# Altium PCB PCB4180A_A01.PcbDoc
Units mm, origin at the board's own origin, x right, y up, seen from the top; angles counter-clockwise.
Board outline 30 x 45 mm, 4 copper layers (Top Layer, Signal Layer 2, Signal Layer 3, Bottom Layer), stack 1.6 mm thick; 82 components, 78 nets, 281 pads, 322 vias.
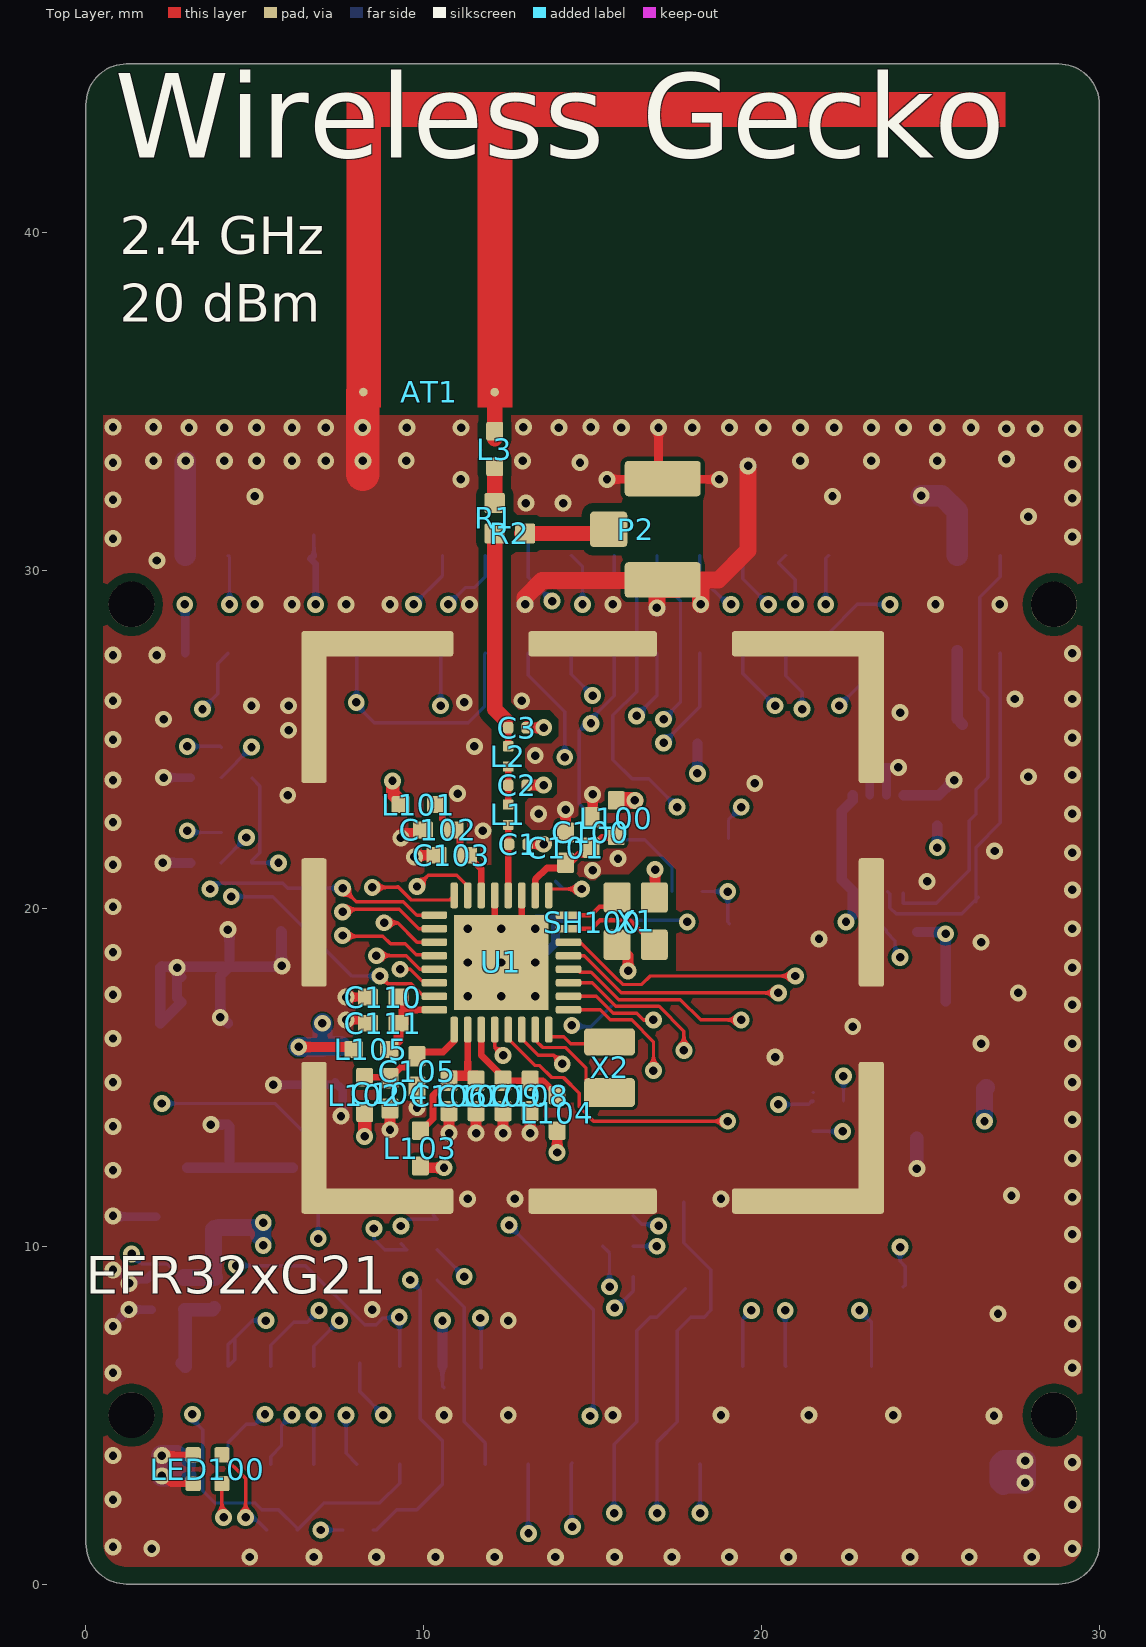
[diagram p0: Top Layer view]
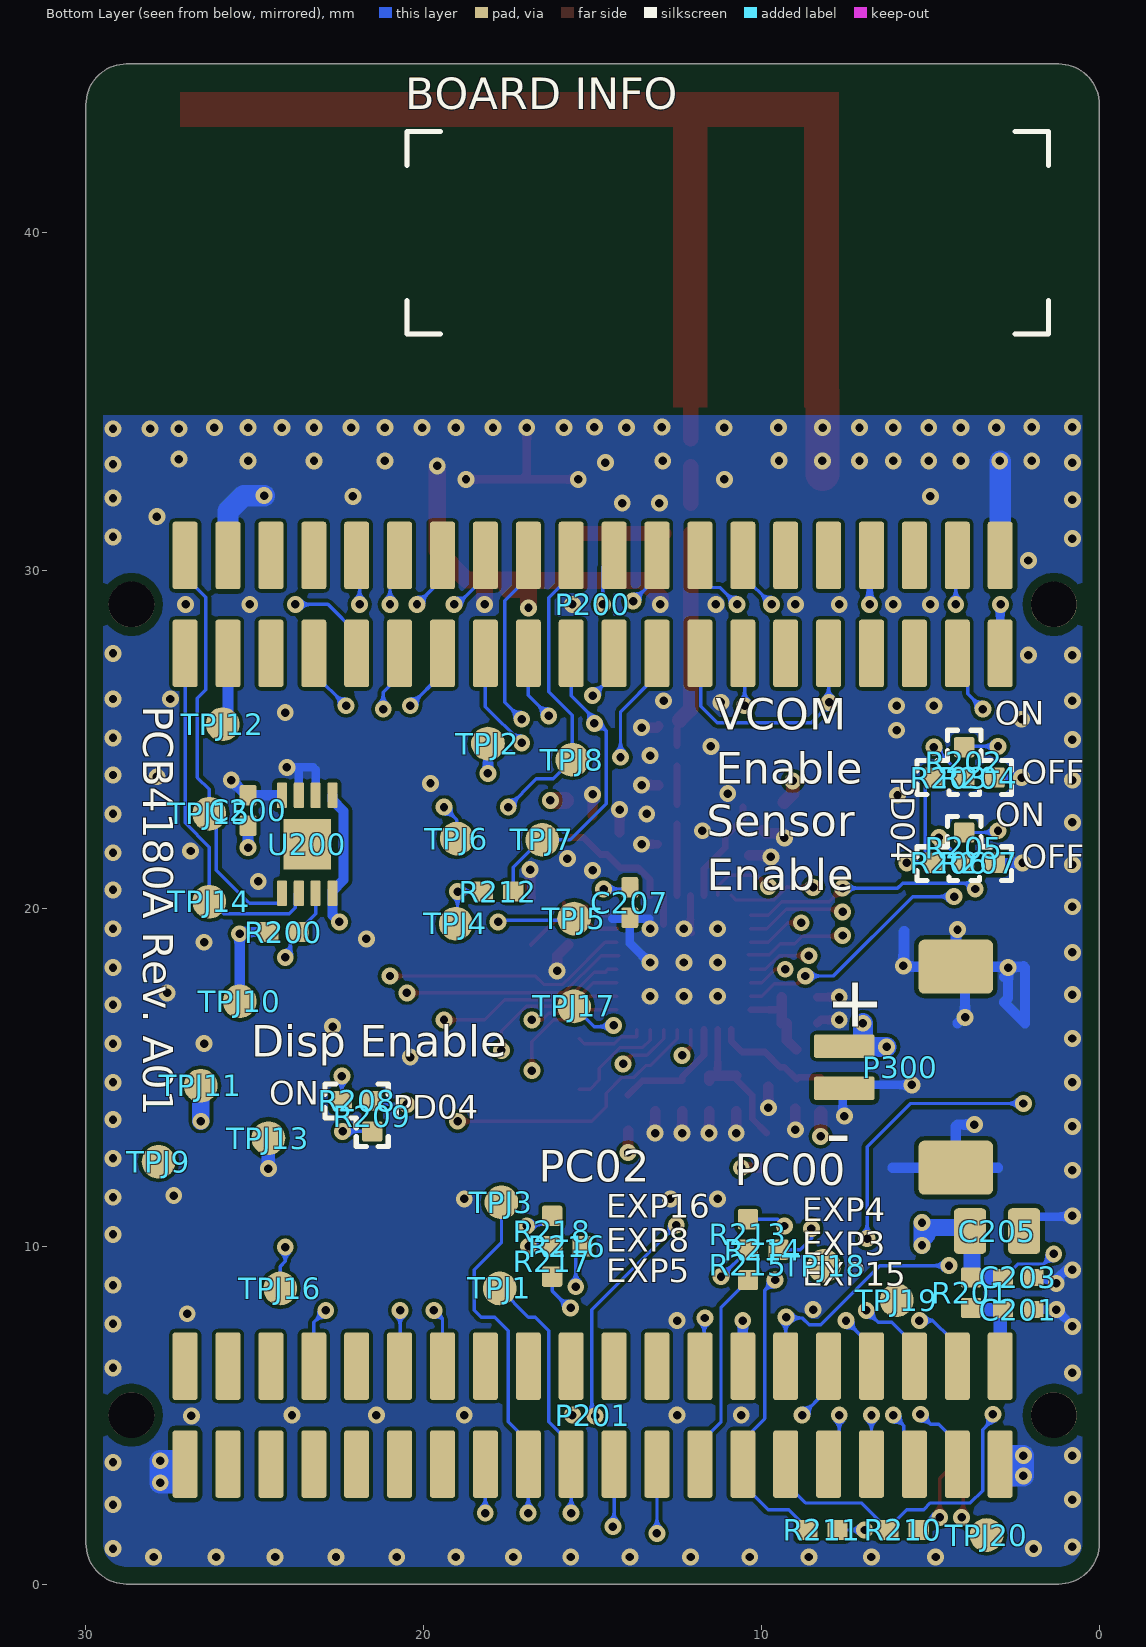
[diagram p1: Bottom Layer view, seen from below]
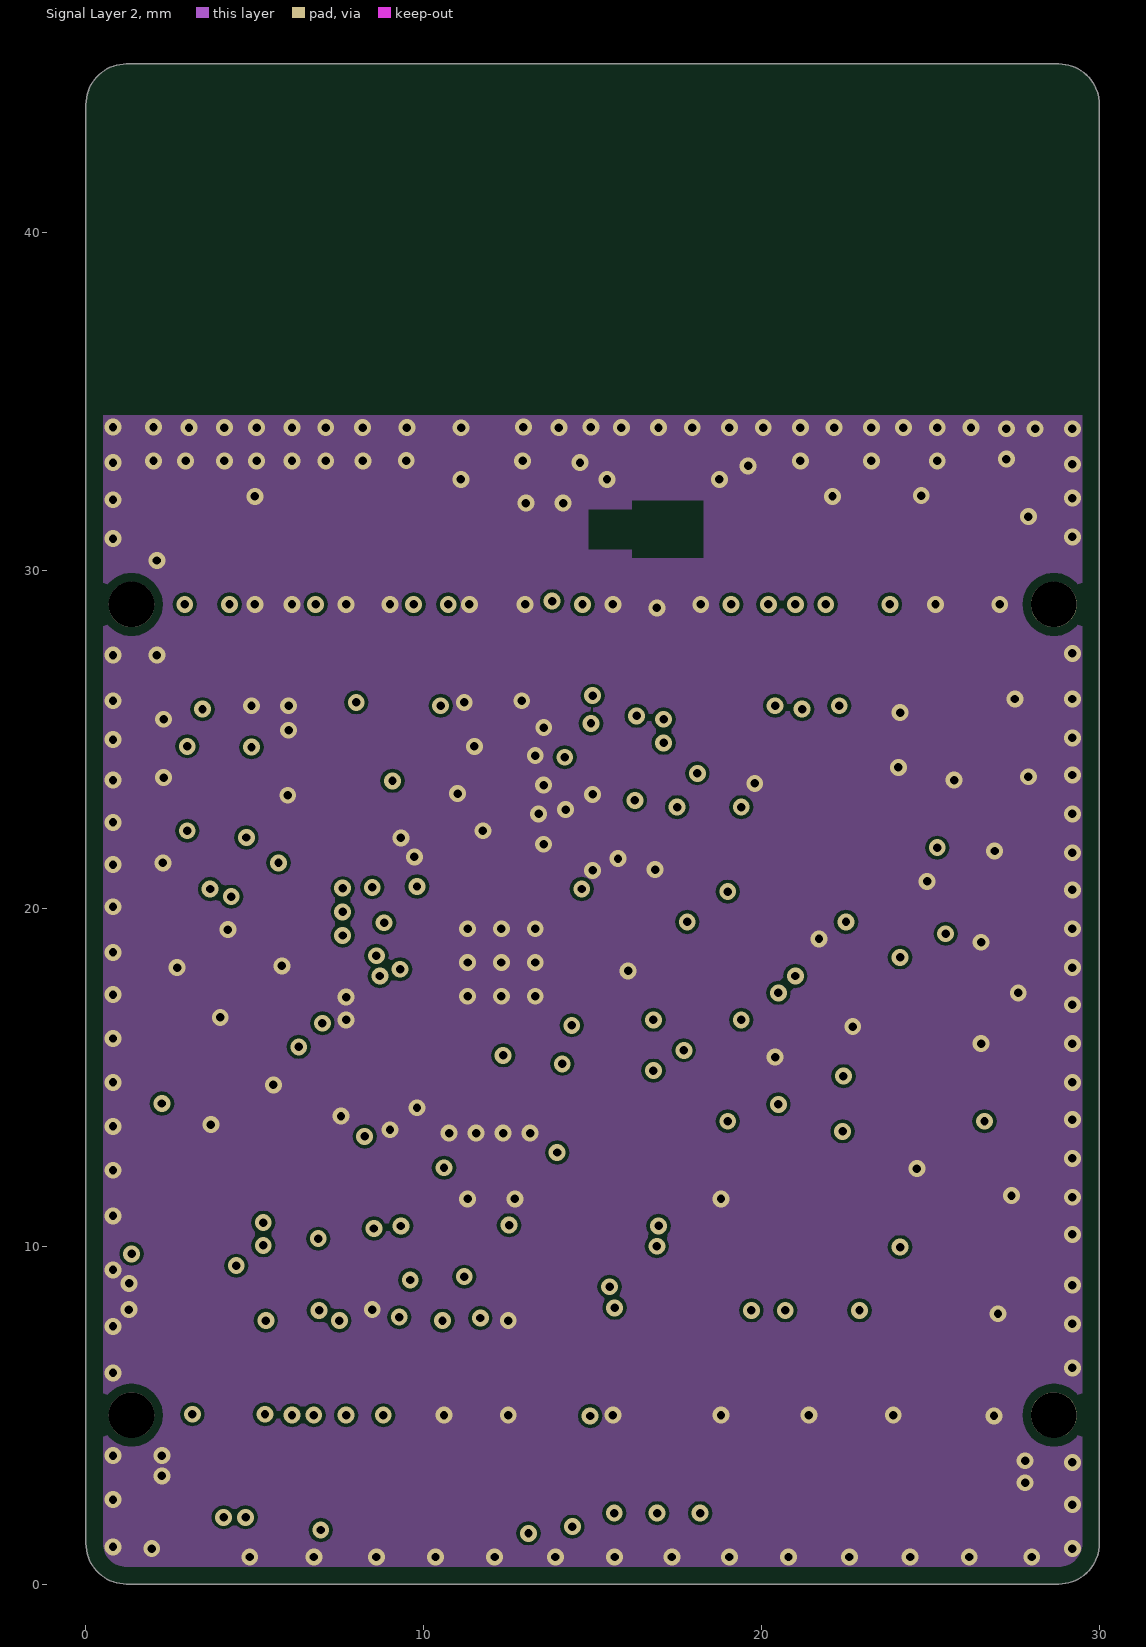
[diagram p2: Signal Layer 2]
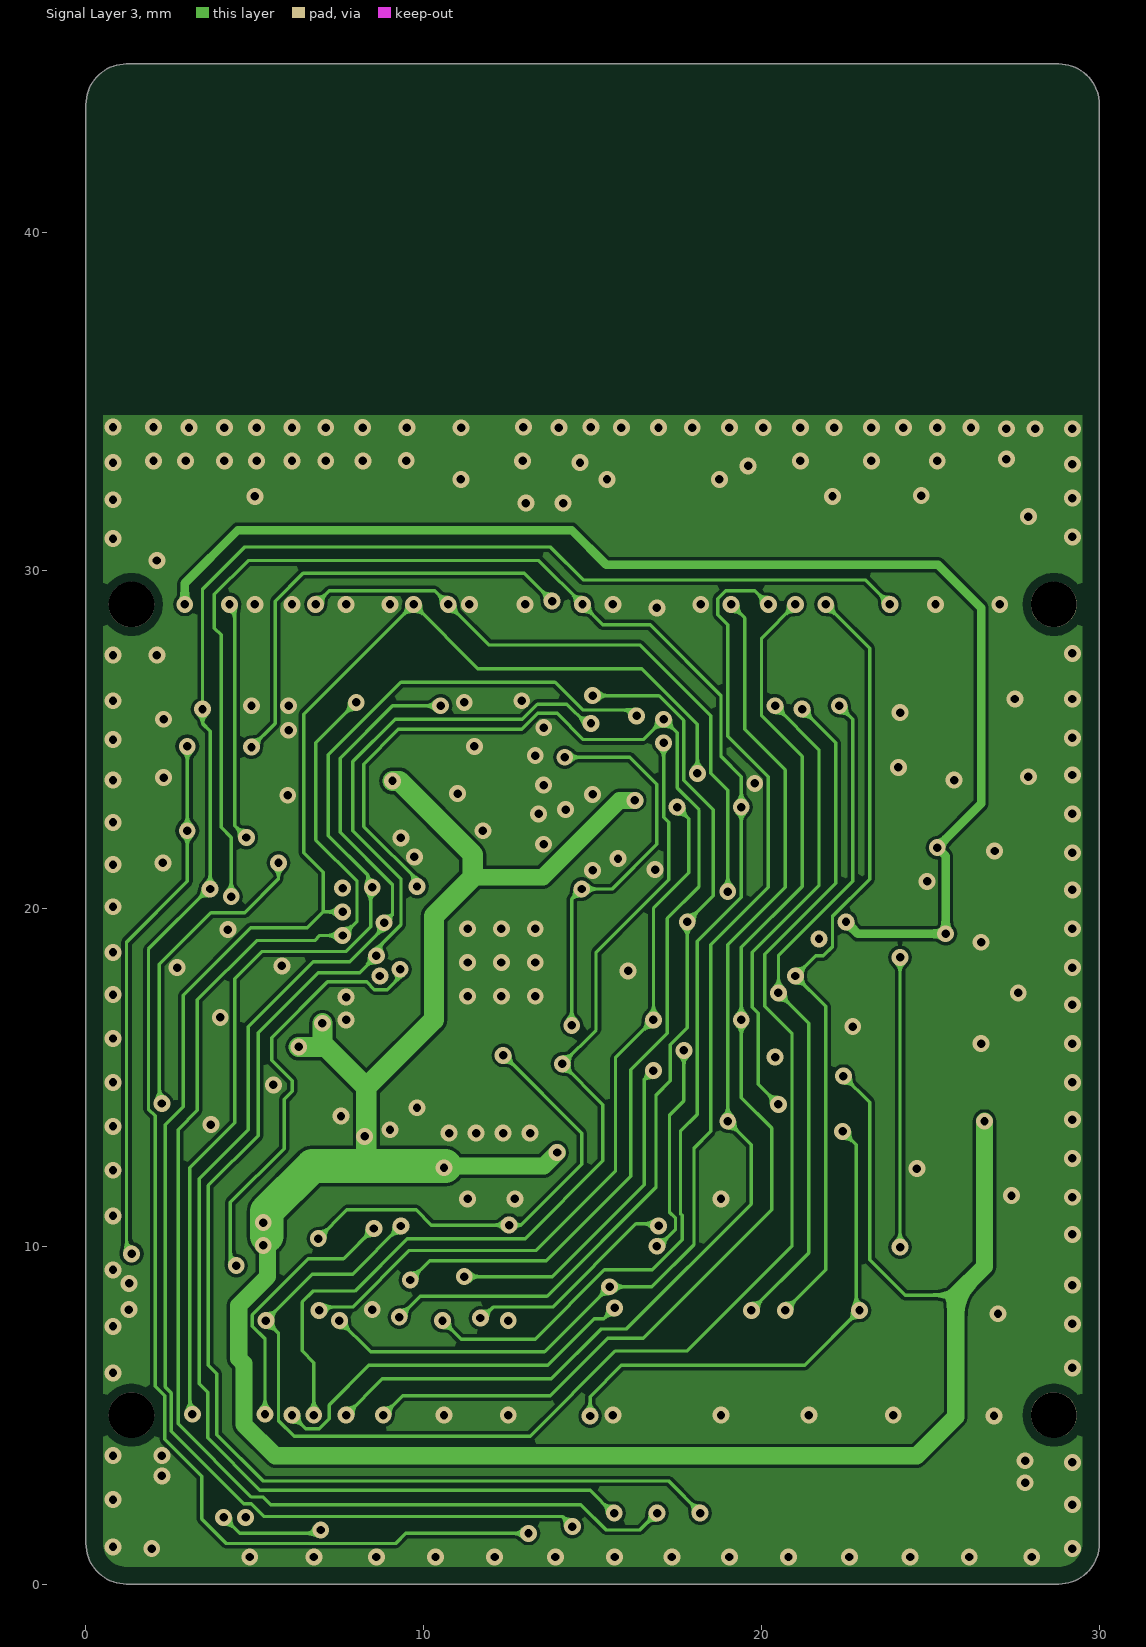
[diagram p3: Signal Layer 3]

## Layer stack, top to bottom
Top Solder: solder mask 0.0102, Solder Resist, Dk 3.5
Top Layer: signal copper 0.035
Dielectric 1: core 0.325, FR-4, Dk 4.2
Signal Layer 2: signal copper 0.018
Dielectric 3: prepreg 0.844, Dk 4.2
Signal Layer 3: signal copper 0.018
Dielectric 2: core 0.325, Dk 4.2
Bottom Layer: signal copper 0.035
Bottom Solder: solder mask 0.0102, Solder Resist, Dk 3.5

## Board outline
0,1.2 0,43.8 cw(c1.2,43.8) 1.2,45 28.8,45 cw(c28.8,43.8) 30,43.8 30,1.2 cw(c28.8,1.2) 28.8,0 1.2,0 cw(c1.2,1.2)

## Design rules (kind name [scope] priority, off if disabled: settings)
AcuteAngle [All] p1: minimum=7.00000000000000E+0001 checktracksonly=FALSE
BoardOutlineClearance [All] p1: gap=0.5
Clearance Clearance_to_Holes [InPadClass('NPTH')] p1: gap=0.254
Clearance Clearance_50Ohm [InNetClass('50Ohm') vs InNet('GND')] p2: gap=0.254 except(0.15: Track-SMDPad; 0.2: SMDPad-SMDPad)
Clearance Clearance_1 [All] p3: gap=0.1
Clearance Clerance_Polygon_GND3 [InNamedPolygon('GND_3')] p4: gap=0.127
Clearance Clerance_Polygon_GND2 [InNamedPolygon('GND_2')] p5: gap=0.127
Clearance Clerance_Polygon_GND1 [InNamedPolygon('GND_1')] p6: gap=0.127
Clearance Clerance_Polygon_GND4 [InNamedPolygon('GND_4')] p7: gap=0.127
HoleToHoleClearance HoleToHoleClearance_ANT1toPAD [Incomponent ('ANT1') vs ISpad] p1: gap=0 allowstackedmicrovias=TRUE
HoleToHoleClearance HoleToHoleClearance_R1toR2_1 [Incomponent ('R1') vs Incomponent ('R2')] p2: gap=0 allowstackedmicrovias=TRUE
HoleToHoleClearance HoleToHoleClearance_U1toVIA_1 [InComponent ('U1') vs IsVia] p3: gap=0 allowstackedmicrovias=TRUE
HoleToHoleClearance [All] p4: gap=0.254 allowstackedmicrovias=TRUE
MinimumSolderMaskSliver [All] p1: minsoldermaskwidth=0.102
PolygonConnect Polygon_VIA_Connect [IsVia] p1: connectstyle=Direct reliefconductorwidth=0.254 reliefentries=4 polygonreliefangle="90 Angle" airgapwidth=0.254
PolygonConnect PolygonConnect_SH100 [InComponent('SH100')] p2: connectstyle=Direct reliefconductorwidth=0.254 reliefentries=4 polygonreliefangle="90 Angle" airgapwidth=0.127
PolygonConnect [All] p3: connectstyle=NoConnect reliefconductorwidth=0.254 reliefentries=4 polygonreliefangle="90 Angle" airgapwidth=0.127
RoutingVias [All] p1: holewidth=0.3 width=0.65 viastyle="Through Hole" minholewidth=0.25 minwidth=0.5 maxholewidth=1 maxwidth=1.5
ShortCircuit ShortCircuit_ANTtoPAD [InNet('NetAT1_1') vs InNet('GND')] p1: allowed=TRUE
ShortCircuit ShortCircuit_R1toR2_1 [Incomponent ('R1') vs Incomponent ('R2')] p2: allowed=TRUE
ShortCircuit [All] p3: allowed=FALSE
SilkToSilkClearance [All] p1: silktosilkclearance=0.102
SilkToSolderMaskClearance [IsPad] p1: minsilkscreentomaskgap=0.102 clearancetoexposedcopper=TRUE
SolderMaskExpansion [All] p1: expansion=0.051
Width 50ohm [InNet('50R*')] p1: maxlimit=0.457 minlimit=0.457 preferedwidth=0.457
Width [All] p2: maxlimit=5.08 minlimit=0.1 preferedwidth=0.125
25 further rules are at their usual default settings.

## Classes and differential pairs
pad class NPTH: P200-M1 P200-M2 P201-M1 P201-M2
net class 50Ohm: 50R_IFA 50R_LANT2 50R_P2 50R_R1

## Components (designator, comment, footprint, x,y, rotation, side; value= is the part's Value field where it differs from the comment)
AT1 "INVERTED_F" EM358x_INVERTED_F 7.714,34.835 r0 top net-tie
C1 "2P3" C0201_L 12.8,21.9 r0 top
C2 "0P8" C0201_L 12.775,23.65 r0 top
C3 "0P3" C0201_L 12.775,25.35 r0 top
C100 "47N" C0402_L 14.95,22.25 r90 top
C101 "12P" C0402_L 14.2,21.8 r90 top
C102 "47N" C0402_L 10.425,22.325 r180 top
C103 "12P" C0402_L 10.825,21.575 r180 top
C104 "2U2" C0402_L 9,14.525 r270 top
C105 "100N" C0402_L 9.8,15.175 r270 top
C106 "1U" C0402_L 10.75,14.45 r270 top
C107 "10N" C0402_L 11.55,14.45 r270 top
C108 "1U" C0402_L 13.15,14.45 r270 top
C109 "100N" C0402_L 12.35,14.45 r270 top
C110 "100N" C0402_L 8.8,17.375 r180 top
C111 "1U" C0402_L 8.8,16.6 r180 top
C200 "100N" C0402_L 25.2,22.9 r90 bottom locked
C201 "100N" C0402_L 2.4,8.125 r180 bottom
C203 "100N" C0402_L 2.4,9.075 r180 bottom
C205 "10U" C0805_L 3.025,10.45 r180 bottom
C207 "100N" C0402_L 13.9,20.175 r270 bottom
Designator39 "Comment" PCB_SPEC_4_LAYER -68.7,108.2 r0 top
L1 "2N3" COIL_0201_L 12.5,22.775 r90 top
L2 "1N1" COIL_0201_L 12.5,24.5 r90 top
L3 "0R" COIL_0402_L 12.1,33.6 r90 top
L100 "9N1" COIL_0402_L 15.7,22.675 r270 top
L101 "9N1" COIL_0402_L 9.85,23.075 r0 top
L102 "0R" COIL_0402_L 8.25,14.475 r90 top
L103 "0R" COIL_0402_L 9.9,12.9 r90 top
L104 "0R" COIL_0402_L 13.95,13.95 r90 top
L105 "0R" COIL_0402_L 8.45,15.825 r180 top
LED100 "SML-P24" LED_ROHM_SML-P24 3.6,3.4 r180 top
P2 "U.FL" COAX_HIROSE_U.FL_CL331-0471 17.075,31.225 r90 top
P200 "SOCKET_2X20_1.27MM_SMD" SAM_SFC-120-T2-D-A-2X20_SNUM 15,29 r0 bottom locked
P201 "SOCKET_2X20_1.27MM_SMD" SAM_SFC-120-T2-D-A-2X20_SNUM 15,5 r0 bottom locked
P300 "DF13A-2P-1.25H" Header_DF13A-2P-1.25H 4.25,15.3 r270 bottom
R1 "0R" R0402_L 12.1,31.55 r90 top
R2 "0R" R0402_L 12.55,31.1 r0 top
R200 "10K" R0402_L 24.15,19.3 r0 bottom locked
R201 "0R" R0402_L 3.8,8.625 r90 bottom
R202 "0R" R0402_L 4,24.325 r90 bottom
R203 "0R" R0402_L 4.45,23.875 r180 bottom
R204 "0R" R0402_L 3.55,23.875 r0 bottom
R205 "0R" R0402_L 4,21.8 r270 bottom
R206 "0R" R0402_L 4.45,21.35 r180 bottom
R207 "0R" R0402_L 3.55,21.35 r180 bottom
R208 "0R" R0402_L 21.975,14.3 r180 bottom
R209 "0R" R0402_L 21.525,13.85 r90 bottom
R210 "2K" R0402_L 5.8,1.6 r180 bottom
R211 "2K" R0402_L 8.2,1.6 r180 bottom
R212 "0R" R0402_L 17.8,20.5 r180 bottom
R213 "0R" R0402_L 10.4,10.35 r90 bottom
R214 "0R" R0402_L 9.95,9.9 r180 bottom
R215 "0R" R0402_L 10.4,9.45 r270 bottom
R216 "0R" R0402_L 15.75,10 r180 bottom
R217 "0R" R0402_L 16.2,9.55 r270 bottom
R218 "0R" R0402_L 16.2,10.45 r90 bottom
SH100 "RF_SHIELD_FRAME_BMI-S-202-F" LAIRD_BMI-S-202-F 15,19.587 r90 top locked
TPJ1 "TPJ_SMD" TP_1.0_SMD#1 17.75,8.75 r90 bottom locked
TPJ2 "TPJ_SMD" TP_1.0_SMD#1 18.1,24.88 r90 bottom locked
TPJ3 "TPJ_SMD" TP_1.0_SMD#1 17.7,11.3 r90 bottom locked
TPJ4 "TPJ_SMD" TP_1.0_SMD#1 19.05,19.55 r90 bottom locked
TPJ5 "TPJ_SMD" TP_1.0_SMD#1 15.55,19.7 r90 bottom locked
TPJ6 "TPJ_SMD" TP_1.0_SMD#1 19.02,22.07 r90 bottom locked
TPJ7 "TPJ_SMD" TP_1.0_SMD#1 16.49,22.03 r90 bottom locked
TPJ8 "TPJ_SMD" TP_1.0_SMD#1 15.6,24.4 r90 bottom locked
TPJ9 "TPJ_SMD" TP_1.0_SMD#1 27.85,12.5 r90 bottom locked
TPJ10 "TPJ_SMD" TP_1.0_SMD#1 25.45,17.25 r90 bottom locked
TPJ11 "TPJ_SMD" TP_1.0_SMD#1 26.6,14.75 r90 bottom locked
TPJ12 "TPJ_SMD" TP_1.0_SMD#1 25.95,25.45 r90 bottom locked
TPJ13 "TPJ_SMD" TP_1.0_SMD#1 24.6,13.2 r90 bottom locked
TPJ14 "TPJ_SMD" TP_1.0_SMD#1 26.35,20.2 r90 bottom locked
TPJ15 "TPJ_SMD" TP_1.0_SMD#1 26.35,22.8 r90 bottom locked
TPJ16 "TPJ_SMD" TP_1.0_SMD#1 24.25,8.75 r90 bottom locked
TPJ17 "TPJ_SMD" TP_1.0_SMD#1 15.55,17.1 r90 bottom locked
TPJ18 "TPJ_SMD" TP_1.0_SMD#2 8.15,9.42 r90 bottom locked
TPJ19 "TPJ_SMD" TP_1.0_SMD#2 6,8.4 r90 bottom locked
TPJ20 "TPJ_SMD" TP_1.0_SMD#1 3.34,1.45 r90 bottom locked
U1 "EFR32MG21A020F1024IM32" QFN32_M040_4.0X4.0_EP_SL 12.3,18.4 r180 top locked
U200 "24AA024" 8-TDFN 23.45,21.9 r0 bottom locked
X1 "38.400MHz" KDS_DSX211SH_2016 16.275,19.625 r270 top
X2 "32.768 kHz" X_MCS_CM8V-T1A 15.5,15.3 r270 top

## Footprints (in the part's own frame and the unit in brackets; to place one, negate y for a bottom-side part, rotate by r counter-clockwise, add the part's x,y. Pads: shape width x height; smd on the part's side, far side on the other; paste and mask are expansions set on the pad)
8-TDFN [mm] "TDFN8_M050_2.0x3.0_EP"
  rrect20% 0.3x0.75 smd mask+0.051: 1(-0.75,-1.45) 2(-0.25,-1.45) 3(0.25,-1.45) 4(0.75,-1.45) 5(0.75,1.45) 6(0.25,1.45) 7(-0.25,1.45) 8(-0.75,1.45)
  rect 1.4x1.5 smd mask+0.051: 9(0,0)
  body extent -1,-1.5 1,1.5, height 1
C0201_L [mm] "Capacitor, Chip; 0.60 mm L X 0.30 mm W X 0.33 mm H body"
  rrect52% 0.31x0.34 smd: 1(-0.275,0) 2(0.275,0)
  body extent -0.3,-0.15 0.3,0.15, height 0.3
C0402_L [mm] "Chip Capacitor, 2-Leads, Body 1.0x0.5mm, IPC High Density"
  rrect20% 0.6x0.5 smd mask+0.051: 1(-0.45,0) 2(0.45,0)
  body extent -0.5,-0.25 0.5,0.25, height 0.6
C0805_L [mm] "Capacitor, 0805"
  rrect25% 0.95x1.35 smd: 1(-0.8,0) 2(0.8,0)
  body extent -1.1,-0.72 1.1,0.72, height 1.45
COAX_HIROSE_U.FL_CL331-0471 [mm] "COAX_HIROSE_U.FL_CL331-0471"
  rrect20% 1.05x1.1 smd mask+0.051: 1(0,1.6)
  rrect20% 1.05x2.25 smd mask+0.051: 2(-1.5,0) 3(1.5,0)
  Top Layer pour cut-out: -0.85,0.9 0.85,0.9 0.85,0.9 0.85,-1.2 -0.85,-1.2 -0.85,-1.2
  body extent -1.3,-1.55 1.3,1.3, height 0.9
COIL_0201_L [mm] "JELF243C-0021"
  rrect10% 0.3x0.3 smd: 1(-0.3,0) 2(0.3,0)
  body extent -0.32,-0.17 0.32,0.17, height 0.33
COIL_0402_L [mm] "COIL_0402_L"
  rrect20% 0.55x0.5 smd mask+0.051: 1(-0.525,0) 2(0.525,0)
  body extent -0.5,-0.25 0.5,0.25, height 0.5
EM358x_INVERTED_F [mil] "F-ANTENNA INVERSE 19.5 mm"
  round 10 smd paste-10 mask-10: 1(172.68,17.72) 2(19.68,17.85)
  Top Layer region: 0,367.2 767.72,367.2 767.72,327.07 193,327.07 193,0 153,0 153,327.07 40,327.07 40,0 20,0 0,0
Header_DF13A-2P-1.25H [mm] "Hirose DF13A-2P-1.25H"
  rrect20% 0.7x1.8 smd: 1(-0.625,-3.3) 2(0.625,-3.3)
  rrect20% 1.6x2.2 smd: 3(-2.975,0) 4(2.975,0)
  body extent -3.58,-3.8 3.57,2.7, height 3.58
KDS_DSX211SH_2016 [mm] "Copy of Silabs CE  X_KDS_DSX211SH_2.0X1.65-4"
  rrect20% 0.9x0.8 smd mask+0.051: 1(-0.7,-0.55) 2(0.7,-0.55) 3(0.7,0.55) 4(-0.7,0.55)
  body extent -1.07,-0.87 1.08,0.88, height 0.5
LAIRD_BMI-S-202-F [mm] "laired BMI-S-202-F"
  rrect20% 0.75x4.5 smd paste+0 mask+0.05: 1(-8.25,-6.375) 1(-8.25,6.375) 1(8.25,-6.375) 1(8.25,6.375)
  rrect20% 0.75x3.8 smd paste+0 mask+0.05: 1(-8.25,0) 1(8.25,0)
  rrect20% 4.5x0.75 smd paste+0 mask+0.05: 1(-6.375,8.25) 1(-6.375,-8.25) 1(6.375,8.25) 1(6.375,-8.25)
  rrect20% 3.8x0.75 smd paste+0 mask+0.05: 1(0,8.25) 1(0,-8.25)
  body extent -8.6,-8.6 8.6,8.6, height 5.5
LED_ROHM_SML-P24 [mm] "LED. Rohm SML-P24MUW, Dual"
  rrect25% 0.45x0.45 smd: 1(-0.425,0.425) 2(-0.425,-0.425) 3(0.425,-0.425) 4(0.425,0.425)
  body extent -0.5,-0.5 0.5,0.5, height 0.31
PCB_SPEC_4_LAYER [mm]
QFN32_M040_4.0X4.0_EP_SL [mm]
  rrect50% 1.1x1.1 on Top Paste: 0(-0.65,0.65) 0(-0.65,-0.65) 0(0.65,0.65) 0(0.65,-0.65)
  rect 2.8x2.8 smd paste-10: 0(0,0)
  rrect50% 0.76x0.22 smd: 1(-1.985,1.4) 2(-1.985,1) 3(-1.985,0.6) 4(-1.985,0.2) 5(-1.985,-0.2) 6(-1.985,-0.6) 7(-1.985,-1) 8(-1.985,-1.4) 17(1.985,-1.4) 18(1.985,-1) 19(1.985,-0.6) 20(1.985,-0.2) 21(1.985,0.2) 22(1.985,0.6) 23(1.985,1) 24(1.985,1.4)
  rrect50% 0.22x0.76 smd: 9(-1.4,-1.985) 10(-1,-1.985) 11(-0.6,-1.985) 12(-0.2,-1.985) 13(0.2,-1.985) 14(0.6,-1.985) 15(1,-1.985) 16(1.4,-1.985) 25(1.4,1.985) 26(1,1.985) 27(0.6,1.985) 28(0.2,1.985) 29(-0.2,1.985) 30(-0.6,1.985) 31(-1,1.985) 32(-1.4,1.985)
  body extent -2,-2 2,2, height 0.56
R0402_L [mm] "Chip Resistor, 2-Leads, Body 1.0x0.5mm, IPC High Density"
  rrect20% 0.6x0.6 smd mask+0.051: 1(-0.45,0) 2(0.45,0)
  body extent -0.5,-0.25 0.5,0.25, height 0.6
SAM_SFC-120-T2-D-A-2X20_SNUM [mm]
  rrect20% 0.74x2 smd mask+0.05: 1(-12.065,1.45) 2(-12.065,-1.45) 3(-10.795,1.45) 4(-10.795,-1.45) 5(-9.525,1.45) 6(-9.525,-1.45) 7(-8.255,1.45) 8(-8.255,-1.45) 9(-6.985,1.45) 10(-6.985,-1.45) 11(-5.715,1.45) 12(-5.715,-1.45) 13(-4.445,1.45) 14(-4.445,-1.45) 15(-3.175,1.45) 16(-3.175,-1.45) 17(-1.905,1.45) 18(-1.905,-1.45) 19(-0.635,1.45) 20(-0.635,-1.45) 21(0.635,1.45) 22(0.635,-1.45) 23(1.905,1.45) 24(1.905,-1.45) 25(3.175,1.45) 26(3.175,-1.45) 27(4.445,1.45) 28(4.445,-1.45) 29(5.715,1.45) 30(5.715,-1.45) 31(6.985,1.45) 32(6.985,-1.45) 33(8.255,1.45) 34(8.255,-1.45) 35(9.525,1.45) 36(9.525,-1.45) 37(10.795,1.45) 38(10.795,-1.45) 39(12.065,1.45) 40(12.065,-1.45)
  round 1.35 hole 1.35 unplated paste-5.563 mask-5.563: M1(13.652,0) M2(-13.652,0)
  body extent -14.65,-1.58 14.65,2.25, height 4.57
TP_1.0_SMD#1 [mm] "Test Point, 1.0 mm, SMD"
  round 1 smd paste-0.501: 1(0,0)
  body extent -0.2,-0.2 0.2,0.2, height 0.01
TP_1.0_SMD#2 [mm] "Test Point, 1.0 mm, SMD"
  round 1 smd paste-0.501 mask-1: 1(0,0)
  body extent -0.2,-0.2 0.2,0.2, height 0.01
X_MCS_CM8V-T1A [mm] "Crystal MCS CM8V-T1A (2 pin)"
  rrect25% 0.8x1.5 smd mask+0.051: 1(-0.75,0)
  rrect25% 0.85x1.5 smd mask+0.051: 2(0.75,0)
  body extent -1,-0.6 1,0.6, height 0.95

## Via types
v1: diameter 0.5, hole 0.25, Top Layer to Bottom Layer, tented both sides, 322 vias

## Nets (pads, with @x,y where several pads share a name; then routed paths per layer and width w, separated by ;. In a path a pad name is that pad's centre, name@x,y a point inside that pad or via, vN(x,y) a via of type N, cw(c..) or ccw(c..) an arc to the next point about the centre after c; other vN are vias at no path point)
3V3: C200.1 P200.1 R200.2 TPJ10.1 U200.1 U200.8 | length 48.3
  Signal Layer 3 w0.254: v1(2.925,29) 2.925,29.625 4.5,31.2 14.375,31.2 15.4,30.175 25.225,30.175 26.5,28.9 26.5,23.1 25.213,21.812 v1(25.2,21.8) 25.45,21.55 v1(25.45,19.25) 22.85,19.25 v1(22.5,19.6)
  Signal Layer 3 w0.305: v1@25.2,21.825 25.212,21.812 v1@25.225,21.8
  Bottom Layer w0.254: v1(2.925,29) 2.95,29 2.975,28.975 2.935,28.935 P200.1
  Bottom Layer w0.305: v1(22.5,19.6) 22.7,19.8 U200.8 ; U200.8@22.7,20.525 22.375,20.85 22.375,22.875 22.7,23.2 U200.1 ; R200.2 25.4,19.3 v1(25.45,19.25) TPJ10.1 ; v1(25.2,21.8) C200.1
5V: P200.37 TPJ12.1 | length 2.2
  Bottom Layer w0.33: P200.37@25.795,27.635 P200.37 25.795,25.605 TPJ12.1
50R_IFA: AT1.1 L3.2 | length 1.4
  Top Layer w0.457: L3.2@12.1,33.9 AT1.1
50R_LANT2: L3.1 R1.2 | length 1.1
  Top Layer w0.457: R1.2 L3.1
50R_P2: P2.1 R2.2 | length 2.7
  Top Layer w0.457: R2.2@12.9,31.1 R2.2 P2.1@15.6,31.1
50R_R1: C3.1 L2.2 R1.1 R2.1 | length 6.2
  Top Layer w0.203: L2.2@12.5,24.825 C3.1@12.5,25.325
  Top Layer w0.457: R2.1 12.1,25.9 12.425,25.575
BOARD_ID_SCL: P200.39 TPJ14.1 U200.6 | length 11.1
  Bottom Layer w0.1: U200.6@23.741,20.5 23.8,20.441 23.8,20.025 23.983,19.842 25.924,19.842 TPJ14.1@26.35,20.269 ; TPJ14.1 TPJ14.1@26.35,20.269 ; TPJ14.1@26.41,20.328 TPJ14.1@26.35,20.269 ; P200.39@27.05,27.535 P200.39 27.065,22.531 26.35,21.816 TPJ14.1@26.35,20.269
BOARD_ID_SDA: P200.40 TPJ15.1 U200.5 | length 12.5
  Bottom Layer w0.1: U200.5 24.2,20.156 25.169,20.156 26.147,21.134 26.147,22.597 TPJ15.1 26.35,23.525 26.7,23.875 26.7,26.225 26.455,26.47 26.455,29.21 27.065,29.82 P200.40
BOARD_ID_WP: R200.1 TPJ16.1 U200.7 | length 12
  Signal Layer 3 w0.1: v1@24.1,10.05 v1(24.1,18.55)
  Bottom Layer w0.1: U200.7 23.2,19.845 23.7,19.344 R200.1 23.95,19.05 23.95,18.725 24.1,18.575 v1(24.1,18.55) ; v1(24.1,9.975) 24.1,9.55 24.25,9.4 24.25,8.85 TPJ16.1@24.2,8.8
EFR32_PA00: P200.3 P200.31 P201.17 U1.17 | length 74.7
  Top Layer w0.1: v1(7.6,20.6) 8,20.2 9.399,20.2 9.799,19.8 U1.17
  Signal Layer 3 w0.1: v1@3.65,20.6 1.85,18.8 1.85,14.059 2.05,13.859 2.05,5.85 2.327,5.573 2.327,4.289 3.425,3.191 3.425,1.925 4.15,1.2 9.166,1.2 9.466,1.5 v1(13.1,1.5) ; v1(3.675,20.575) 3.675,25.25 3.45,25.475 v1(3.45,25.9) 3.45,29.45 4.7,30.7 13.75,30.7 14.725,29.725 23.075,29.725 v1(23.8,29)
  Bottom Layer w0.1: v1(3.45,25.9) 3.9,26.35 3.9,27.245 P200.3 ; v1@3.6,20.6 3.75,20.75 5.825,20.75 5.975,20.6 v1(7.6,20.6) ; P201.17 13.095,1.505 v1(13.1,1.5) ; P200.31 21.985,28.15 22.835,29 v1(23.8,29)
EFR32_PA01: P200.14 P201.19 TPJ2.1 U1.18 | length 61.6
  Top Layer w0.1: v1(7.6,19.9) 7.676,19.976 9.274,19.976 9.85,19.4 U1.18
  Signal Layer 3 w0.1: v1(7.6,19.9) 7.025,19.9 ; v1@14.35,1.65 v1@14.4,1.6 ; v1(14.4,1.7) 14.1,2 6.785,2 5.266,2 4.891,2.375 4.675,2.375 2.527,4.523 2.527,5.656 2.35,5.833 2.35,13.6 2.875,14.125 2.875,17.425 4.875,19.425 6.55,19.425 7.025,19.9 ; v1(18.1,24) 18.1,25.449 16.449,27.1 11.6,27.1 v1(9.7,29) 6.45,25.75 6.45,21.65 7.025,21.075 7.025,19.9
  Bottom Layer w0.1: v1(9.7,29) 10.555,29.855 P200.14 ; v1(14.4,1.7) 14.365,1.735 P201.19 P201.19@14.4,3.585
  Bottom Layer w0.3: v1(18.1,24) TPJ2.1
EFR32_PA02: P200.13 P201.21 TPJ1.1 U1.19 | length 51.4
  Top Layer w0.1: v1(8.825,19.576) 9.224,19.576 9.8,19 U1.19
  Signal Layer 3 w0.1: v1(8.825,19.576) 8.825,19.443 7.808,18.425 6.725,18.425 4.8,16.5 4.8,13.45 3.35,12 3.35,5.925 3.6,5.675 3.6,4.325 5.15,2.775 14.925,2.775 v1@15.6,2.1 ; v1(8.825,19.576) 9.075,19.826 9.075,20.7 7.525,22.25 7.525,24.45 9.075,26 v1(10.5,26)
  Bottom Layer w0.1: v1(10.5,26) 10.5,27.525 P200.13@10.55,27.575 ; v1@15.635,2.105 P201.21 15.635,4.135 16.3,4.8 16.3,7.5 16.7,7.9 16.9,7.9 TPJ1.1
  other v1: 15.64,2.1
EFR32_PA03: P200.9 P200.15 P201.23 TPJ3.1 U1.20 | length 62.4
  Top Layer w0.1: v1(7.6,19.2) 7.624,19.176 8.79,19.176 9.016,18.95 9.45,18.95 9.775,18.625 U1.20@10.4,18.625
  Signal Layer 3 w0.1: v1(8,26.1) 6.8,24.9 6.8,22.025 8.025,20.8 8.025,19.625 v1(7.6,19.2) 6.925,19.2 6.775,19.05 5.05,19.05 3.3,17.3 3.3,14.025 2.727,13.452 2.727,4.748 4.9,2.575 5.25,2.575 5.475,2.35 14.65,2.35 15.4,1.6 16.4,1.6 v1@16.9,2.1
  Bottom Layer w0.1: v1@8,26 v1@8.015,26.015 ; P200.9 v1@8.015,26.015 ; P200.15 11.8,27.525 11.8,25.984 11.316,25.5 8.53,25.5 v1@8.015,26.015 ; v1(16.91,2.1) 16.905,2.105 P201.23 16.905,4.205 17.5,4.8 17.5,7.5 17.9,7.9 18.3,7.9 18.5,8.1 18.5,9.3 17.7,10.1 TPJ3.1
EFR32_PA04: P200.21 P201.25 R212.2 TPJ7.1 U1.21 | length 59.6
  Top Layer w0.1: v1(8.6,18.6) 8.604,18.604 9.48,18.604 9.884,18.2 U1.21
  Signal Layer 3 w0.1: v1@14.95,25.333 v1@14.954,25.329 ; v1@14.951,25.334 v1(14.951,25.476) 14.807,25.476 14.233,26.05 13.366,26.05 12.916,25.6 9.15,25.6 7.9,24.35 7.9,22.3 9.325,20.875 9.325,19.51 8.6,18.785 v1(8.6,18.6) 8.1,18.1 6.875,18.1 5.098,16.323 5.098,13.273 3.625,11.8 3.625,6.475 3.875,6.225 3.875,4.425 5.25,3.05 17.25,3.05 v1@18.2,2.1
  Bottom Layer w0.1: P200.21 15.635,26.3 14.6,25.265 14.6,23.1 15.67,22.03 TPJ7.1 16.536,22.03 17.35,21.216 R212.2 ; P201.25 18.18,3.545 v1(18.18,2.1)
EFR32_PA05: P200.19 P201.12 TPJ5.1 U1.22 | length 51.6
  Top Layer w0.102: v1(9.3,18.2) 9.6,18.2 10,17.8 U1.22
  Signal Layer 3 w0.1: v1@9.337,7.837 9.337,7.962 9.9,8.525 13.65,8.525 16.875,11.75 16.875,14.475 17.3,14.9 17.3,15.966 17.8,16.466 v1(17.8,19.6) 18.575,20.375 18.575,22.925 17.7,23.8 17.7,25.566 16.966,26.3 v1(15,26.3)
  Signal Layer 3 w0.102: v1(4.45,9.425) 4.275,9.601 4.275,11.3 5.866,12.891 5.866,14.349 6.101,14.584 6.101,14.899 5.5,15.5 5.5,16.175 7.15,17.825 8.308,17.825 8.534,17.599 8.924,17.599 9.3,17.975 v1(9.3,18.2)
  Bottom Layer w0.1: P201.12 v1@9.285,7.76 ; P200.19 14.365,26.935 v1(15,26.3)
  Bottom Layer w0.102: v1(4.45,9.425) 6.5,9.425 8.25,7.675 8.592,7.675 8.792,7.875 v1@9.275,7.875 ; TPJ5.1 15.6,19.65 17.55,19.65
  other v1: 9.275,7.9
EFR32_PA06: P200.20 P201.14 TPJ6.1 U1.23 | length 63.8
  Top Layer w0.1: v1(8.7,18) 8.925,17.775 9.625,17.775 10,17.4 U1.23
  Signal Layer 3 w0.1: v1(4.3,20.35) 4.3,22.1 4,22.4 4,28.1 3.8,28.3 3.8,29.3 4.8,30.3 13.4,30.3 v1(14.7,29) 15.3,28.4 16.7,28.4 18.8,26.3 18.8,24.5 19.4,23.9 v1(19.4,23) 19.4,20.334 18.1,19.034 18.1,13.9 17.6,13.4 17.6,10.967 17.654,10.913 17.654,10.188 16.766,9.3 15.35,9.3 13.299,7.249 11.106,7.249 v1(10.555,7.8)
  Bottom Layer w0.1: v1(4.3,20.35) 5.525,20.35 7.875,18 v1(8.7,18) ; P201.14 10.555,5.855 P201.14@10.6,5.81 ; P200.20 14.7,30.115 v1(14.7,29) ; TPJ6.1 19.02,22.62 v1(19.4,23)
  Bottom Layer w0.3: P201.14 v1(10.555,7.8)
EFR32_PB00: P200.23 P201.11 R210.1 U1.16 | length 49
  Top Layer w0.102: v1(8.475,20.625) 9.208,20.625 9.233,20.65 9.634,20.249 10.764,20.249 U1.16
  Signal Layer 3 w0.1: v1(3.15,5.025) 3.275,5.025 3.075,5.225 3.075,12.325 4.4,13.65 4.4,17.925 5.2,18.725 7.691,18.725 8.425,19.46 8.425,20.5 8.475,20.55 v1(8.475,20.625) 8.35,20.75 8.35,20.975 7.175,22.15 7.175,24.55 9.325,26.7 13.887,26.7 14.711,25.876 16.124,25.876 v1(16.3,25.7)
  Bottom Layer w0.1: v1(3.15,5.025) 3.15,4.874 3.455,4.569 3.455,2.761 3.816,2.4 5,2.4 5.2,2.2 5.7,2.2 6.25,1.65 R210.1 7.05,2.4 8.7,2.4 9.285,2.985 P201.11 ; v1(16.3,25.7) 16.905,26.305 P200.23
EFR32_PB01: P200.24 P201.13 R211.1 U1.15 | length 53.6
  Top Layer w0.1: v1(9.8,20.65) 10.127,20.977 10.977,20.977 11.3,20.655 U1.15
  Signal Layer 3 w0.1: v1(9.6,9) 9.6,9.004 10.171,9.575 13.625,9.575 16.125,12.075 16.125,15.225 17.204,16.304 17.204,19.704 18.15,20.65 18.15,22.916 17.5,23.566 17.5,25.2 v1(17.1,25.6) 16.5,25 14.725,25 13.95,25.775 13.374,25.775 12.899,25.3 9.25,25.3 8.225,24.275 8.225,22.425 9.95,20.7 9.9,20.65 v1(9.8,20.65)
  Bottom Layer w0.1: R211.1@8.5,1.6 8.6,1.6 9.2,2.2 9.8,2.2 10.555,2.955 P201.13 10.555,4.245 9.9,4.9 9.9,8.7 v1(9.6,9) ; P200.24 16.905,29.805 17.6,29.11 17.6,26.1 v1(17.1,25.6)
EFR32_PC00: R213.1 R214.1 R215.1 U1.1 | length 14.8
  Top Layer w0.1: U1.1 15.22,17 15.52,16.7 16.154,16.7 16.8,16.054 v1(16.8,15.2)
  Signal Layer 3 w0.1: v1(11.2,9.1) 13.8,9.1 16.525,11.825 16.525,14.925 v1(16.8,15.2)
  Bottom Layer w0.1: R213.1 v1(11.2,9.1)
EFR32_PC01: P200.22 P201.6 TPJ8.1 U1.2 | length 36.7
  Top Layer w0.1: U1.2 15.103,17.4 15.603,16.9 16.3,16.9 16.5,16.7 v1(16.8,16.7)
  Signal Layer 3 w0.1: v1(6.9,8.1) 7,8.2 7.9,8.2 9.575,9.875 13.325,9.875 15.675,12.225 15.675,15.575 v1(16.8,16.7) 16.8,20 17.85,21.05 17.85,22.65 v1(17.5,23)
  Bottom Layer w0.1: P201.6 5.475,7.075 6.15,7.75 6.55,7.75 v1(6.9,8.1) ; P200.22 15.635,29.865 16.3,29.2 16.3,26.417 15.6,25.717 TPJ8.1 16.165,23.835 16.665,23.835 v1(17.5,23)
EFR32_PC02: R216.1 R217.1 R218.1 U1.3 | length 11.6
  Top Layer w0.1: U1.3 14.986,17.8 15.686,17.1 16.966,17.1 17.7,16.366 v1(17.7,15.8)
  Signal Layer 3 w0.1: v1(16.9,10) 16.955,10 17.454,10.499 17.454,10.83 17.275,11.009 17.275,13.875 17.7,14.3 v1(17.7,15.8)
  Bottom Layer w0.1: R216.1 v1(16.9,10)
EFR32_PC03: P200.30 P201.10 U1.4 | length 43.3
  Top Layer w0.1: U1.4 14.556,18.2 14.614,18.142 14.614,18.117 14.952,18.117 15.769,17.3 17.6,17.3 18.2,16.7 v1(19.4,16.7)
  Signal Layer 3 w0.1: v1(8.8,5) 9.375,5.575 13.75,5.575 15.45,7.275 16.5,7.275 20.3,11.075 20.3,13.5 19.4,14.4 v1(19.4,16.7) 19.4,18.85 21.2,20.65 21.2,24.5 20,25.7 20,28 v1(21,29)
  Bottom Layer w0.1: P201.10@8.1,6.535 8.1,5.7 v1(8.8,5) ; P200.30 20.5,30.235 21,29.735 v1(21,29)
EFR32_PC04: P200.33 P201.28 U1.5 | length 30.2
  Top Layer w0.1: U1.5@14.225,18.6 U1.5 14.751,18.6 15.851,17.5 v1(20.5,17.5)
  Signal Layer 3 w0.1: v1(19.7,8.1) 21.4,9.8 21.4,16.6 v1(20.5,17.5) 20.5,18.6 22.7,20.8 22.7,25.6 v1(22.3,26)
  Bottom Layer w0.1: P201.28 19.445,7.845 v1(19.7,8.1) ; v1(22.3,26) 23.25,26.95 P200.33@23.25,27.275
EFR32_PC05: P200.32 P201.30 U1.6 | length 33.8
  Top Layer w0.1: U1.6 14.635,19 15.65,17.985 15.884,17.75 16.45,17.75 16.7,18 v1(21,18)
  Signal Layer 3 w0.1: v1(20.7,8.1) 21.9,9.3 21.9,17.1 v1(21,18) 21.6,18.6 21.83,18.6 22.1,18.87 22.1,19.766 23.2,20.866 23.2,27.7 v1(21.9,29)
  Bottom Layer w0.1: v1(20.7,8.1) 20.7,6.465 P201.30 ; v1(21.9,29) 21.9,30.365 P200.32
EFR32_PD00: U1.32 X2.1 | length 2.1
  Top Layer w0.1: U1.32 13.7,16.204 14.15,16.204 14.354,16 15.25,16 X2.1@15.4,16.15
EFR32_PD01: U1.31 X2.2 | length 3.2
  Top Layer w0.1: U1.31 13.3,16.1 13.515,15.885 14.186,15.885 14.804,15.267 14.804,14.933 14.798,14.927 15.075,14.65 X2.2@15.4,14.65
EFR32_PD02: P200.25 P201.7 U1.30 | length 34.7
  Top Layer w0.1: U1.30 12.9,16.144 13.392,15.652 13.848,15.652 v1(14.1,15.4)
  Signal Layer 3 w0.1: v1(6.745,5) 6.745,6.555 6.4,6.9 6.4,8.35 6.725,8.675 7.966,8.675 9.516,10.225 13,10.225 15.3,12.525 15.3,14.192 14.096,15.396 v1(14.1,15.4) 15.1,16.4 15.1,18.7 17.25,20.85 17.25,22.55 17.1,22.7 v1(17.1,24.9)
  Bottom Layer w0.1: P201.7 v1(6.745,5) ; v1(17.1,24.9) 18.175,25.975 P200.25
EFR32_PD03: P200.26 P201.9 U1.29 | length 45.5
  Top Layer w0.1: U1.29 12.5,16.144 13.294,15.35 13.433,15.35 13.787,14.996 14.137,14.996 14.6,14.533 14.6,14.125 15.025,13.7 v1(19,13.7)
  Signal Layer 3 w0.1: v1(7.7,5) 8.775,6.075 13.775,6.075 15.25,7.55 16,7.55 19.7,11.25 19.7,13 v1(19,13.7) 19,18.925 20.7,20.625 20.7,24.1 19.5,25.3 19.5,28.6 v1(19.1,29)
  Bottom Layer w0.1: v1(7.7,5) 7.7,3.865 P201.9 ; P200.26 18.175,29.825 19,29 v1(19.1,29)
EFR32_PD04: P201.34 R203.1 R206.1 R209.1 U1.28 | length 59.3
  Top Layer w0.1: U1.28 12.1,15.9 v1(12.35,15.65)
  Signal Layer 3 w0.1: v1(2.25,14.225) 2.175,14.3 2.175,18.35 3.7,19.875 4.7,19.875 5.7,20.875 5.7,21.3 5.65,21.35 v1(5.7,21.35) ; v1(6.875,10.225) 7.725,11.075 9.775,11.075 10.225,10.625 v1(12.525,10.625) 12.875,10.625 14.675,12.425 14.675,13.35 12.375,15.65 v1(12.35,15.65) ; v1(14.925,4.975) 14.925,5.55 15.85,6.475 21.275,6.475 v1(22.9,8.1) 22.8,8.2 22.8,13 v1(22.4,13.4)
  Bottom Layer w0.1: v1(2.25,14.225) 5.6,14.225 6.875,12.95 v1(6.875,10.225) ; R203.1@4.925,23.85 5.15,23.625 5.15,21.65 4.9,21.4 R206.1 v1(5.7,21.35) ; v1(12.525,10.625) 15.025,8.125 v1@15.025,4.9 ; R209.1 v1@22.4,13.4 ; v1(22.9,8.1) 23.255,7.745 P201.34
EFR32_RESET: C207.1 P200.17 TPJ17.1 U1.9 | length 18.7
  Top Layer w0.1: U1.9@13.7,20.7 13.7,20.576 v1(14.676,20.576)
  Signal Layer 3 w0.1: v1(14.175,24.475) 16.1,24.475 16.9,23.675 16.9,21.9 15.576,20.576 v1(14.676,20.576) 14.38,20.28 v1(14.38,16.54)
  Bottom Layer w0.1: P200.17 13.095,26.905 14.175,25.825 v1(14.175,24.475) ; C207.1@13.9,20.8 14.124,20.576 v1(14.676,20.576) ; v1@14.4,16.5 14.95,16.5 TPJ17.1
GND: AT1.2 C1.2 C2.2 C3.2 C100.2 C101.2 C102.2 C103.2 C104.2 C105.2 C106.2 C107.2 C108.2 C109.2 C110.2 C111.2 C200.2 C201.2 C203.2 C205.2 C207.2 LED100.3 LED100.4 P2.2 P2.3 P200.2 P200.38 P201.1 P201.39 P300.2 P300.3 P300.4 R204.1 R207.2 SH100.1 TPJ13.1 U1.0@12.3,18.4 U1.11 U1.13 U200.2 U200.3 U200.4 X1.2 X1.4 | length 79.3
  Top Layer w0.2: v1@2.2,3.8 2.225,3.825 LED100.3 ; v1@2.3,3.2 2.525,2.975 LED100.4
  Top Layer w0.203: v1@9.65,21.575 9.7,21.525 v1(9.725,21.525) ; U1.0@12.075,19.275 12.1,19.3 U1.13 ; U1.0@12.9,19.525 U1.11
  Top Layer w0.254: v1(7.7,16.7) 8.25,16.7 C111.2 ; v1(7.7,17.375) C110.2 ; C1.2 13.625,21.9 v1@13.662,21.937 ; v1(15.425,32.7) P2.3@17.05,32.7 ; v1(16.95,34.233) 16.95,32.85 P2.3 P2.3@17.05,32.7 ; v1(18.75,32.7) P2.3@17.05,32.7
  Top Layer w0.3: v1(9.325,22.09) 9.325,22.225 9.875,22.225 C102.2 ; v1@9.65,21.575 C103.2 ; C101.2 v1(14.2,22.925) ; C100.2@15,22.75 v1(15,23.375)
  Top Layer w0.305: C104.2 v1(9,13.45) v1@9.05,13.4 ; v1(9.325,22.09) v1@9.325,22.175 ; v1(9.8,14.1) C105.2 ; v1(10.75,13.35) C106.2 ; v1(11.55,13.35) C107.2 ; v1(12.35,13.35) C109.2 ; C2.2 v1(13.55,23.65) v1@13.6,23.65 ; C3.2@13.05,25.4 13.099,25.351 v1(13.551,25.351) ; v1(13.15,13.35) C108.2 ; X1.2 16.05,18.6 v1(16.05,18.15) ; X1.4 16.85,20.35 v1(16.85,21.15)
  Top Layer w0.508: v1(13,29) 13,29.208 13.496,29.704 P2.2@17.054,29.704 ; v1(16.9,28.9) 16.9,29.55 P2.2@17.054,29.704 ; P2.2@17.075,29.45 P2.2@17.525,29.45 ; v1(18.2,29) 18.2,29.725 ; v1(19.6,33.1) 19.6,30.6 18.725,29.725 18.2,29.725 ; P2.2@17.054,29.704 P2.2 18.2,29.725
  Top Layer w1: 8.192,32.856 v1(8.192,34.233) AT1.2@8.192,35.288
  Bottom Layer w0.254: 0.998,7.85 v1(1.273,8.125) C201.2 ; v1@0.998,9.3 1.273,9.025 1.8,9.025 C203.2@1.95,9.175 ; v1@0.998,10.9 1.023,10.875 C205.2@2.075,10.875 ; v1(2.3,23.875) R204.1 ; v1(5.55,14.775) 7.3,14.775 7.375,14.85 P300.2 7.6,14.625 v1@7.6,13.9 ; v1@13.325,18.4 13.9,18.975 C207.2@13.9,19.7 ; v1@13.325,19.4 13.325,19.7 C207.2@13.9,19.7 ; C207.2 C207.2@13.9,19.7 ; 14.425,19.7 C207.2@13.9,19.7 ; U200.2 23.2,24.1 23.275,24.175 23.7,24.175 ; U200.3 23.7,24.175 ; v1(24.05,24.175) 23.7,24.175
  Bottom Layer w0.3: v1(2.275,21.35) R207.2 ; 2.825,17.975 2.7,18.1 v1(2.7,18.25) 2.7,17.35 2.825,17.225 2.2,16.6 2.2,18.25 2.25,18.3 2.275,18.275 P300.3 ; 3,12.325 P300.4 ; v1(3.7,13.6) 4.2,13.6 4.25,13.55 P300.4 ; 4.2,16.6 3.975,16.825 3.975,18 P300.3 ; v1@4.25,19.325 P300.3 ; v1(5.8,18.3) 5.8,19.3 5.775,19.325 5.775,18.275 P300.3 ; 6.125,12.325 P300.4
  Bottom Layer w0.305: v1(3.05,34.233) v1@3.05,34.25 ; v1(9.5,34.233) v1@9.5,34.25 ; U200.4 C200.2 25.25,23.35 v1(25.7,23.8)
  Bottom Layer w0.4: v1(24.6,12.3) TPJ13.1
  Bottom Layer w0.635: P201.1@2.9,3.25 2.95,3.2 v1(2.25,3.2) v1(2.25,3.8) 2.685,3.8 P201.1 ; P200.2 v1@2.935,33.235 ; v1(24.727,32.222) 25.328,32.222 25.795,31.755 P200.38 ; P201.39 27.065,3.035 27.15,2.95 27.2,3 v1(27.8,3) v1(27.8,3.65) ; P201.39 27.7,3.55 v1(27.8,3.65) ; P201.39 27.165,3.65 v1(27.8,3.65)
  other v1: 4.848,0.8 6.748,0.8 8.598,0.8 10.348,0.8 12.098,0.8 13.898,0.8 15.648,0.8 17.348,0.8 19.048,0.8 20.798,0.8 22.598,0.8 24.398,0.8 26.148,0.8 27.998,0.8 1.948,1.05 29.2,1.05 0.8,1.1 29.2,2.35 0.8,2.5 29.2,3.6 0.8,3.8 26.881,4.977 10.6,5 12.5,5 15.6,5 18.8,5 21.4,5 23.9,5 0.8,6.25 29.2,6.4 0.8,7.625 29.2,7.7 12.5,7.8 27,8 8.475,8.125 29.2,8.85 1.275,8.9 0.8,9.3 29.2,10.35 0.8,10.9 11.3,11.4 12.7,11.4 18.8,11.4 29.2,11.45 27.4,11.5 0.8,12.25 29.2,12.6 0.8,13.55 29.2,13.75 7.55,13.85 0.8,14.85 29.2,14.85 20.4,15.6 26.5,16 29.2,16 0.8,16.15 22.7,16.5 3.975,16.775 29.2,17.15 11.3,17.4 12.3,17.4 13.3,17.4 0.8,17.45 27.6,17.5 29.2,18.25 11.3,18.4 12.3,18.4 13.3,18.4 0.8,18.7 26.5,19 21.7,19.1 4.2,19.375 11.3,19.4 12.3,19.4 13.3,19.4 29.2,19.4 0.8,20.05 29.2,20.55 24.9,20.8 15,21.125 0.8,21.3 15.75,21.475 29.2,21.65 26.9,21.7 13.55,21.9 11.75,22.3 0.8,22.55 13.4,22.8 29.2,22.8 5.975,23.35 11,23.4 19.8,23.7 0.8,23.8 27.9,23.9 29.2,23.95 13.3,24.525 11.5,24.8 0.8,25 29.2,25.05 6,25.275 2.3,25.6 24.1,25.8 4.9,26 6,26 11.2,26.1 0.8,26.15 12.9,26.15 27.5,26.2 29.2,26.2 0.8,27.5 2.1,27.5 29.2,27.55 5,29 6.1,29 7.7,29 9,29 11.35,29 15.6,29 25.15,29 27.05,29 2.1,30.3 0.8,30.95 29.2,31 27.9,31.6 13.025,32 14.125,32 0.8,32.1 29.2,32.15 5,32.2 22.1,32.2 11.1,32.7 29.2,33.15 0.8,33.2 14.625,33.2 2,33.25 2.95,33.25 4.1,33.25 5.05,33.25 6.1,33.25 7.1,33.25 8.2,33.25 12.925,33.25 21.15,33.25 23.25,33.25 25.2,33.25 9.483,33.255 27.25,33.3 27.25,34.2 28.1,34.2 29.2,34.2 4.1,34.233 5.05,34.233 6.1,34.233 7.1,34.233 11.106,34.232 14,34.233 15.85,34.233 17.95,34.233 19.05,34.233 20.05,34.233 21.15,34.233 22.15,34.233 23.25,34.233 24.2,34.233 25.2,34.233 26.2,34.233 0.8,34.25 2,34.25 12.95,34.25 14.95,34.25
N350878: C1.1 L1.1 U1.12 | length 2.1
  Top Layer w0.203: U1.12 L1.1 L1.1@12.5,22.5
N351418: C102.1 C103.1 L101.2 U1.14 | length 3.1
  Top Layer w0.2: L101.2@10.55,23 10.55,22.65 C102.1 11.075,22.125 11.075,21.8 11.7,21.175 U1.14
N351750: U1.7 X1.3 | length 2.9
  Top Layer w0.127: U1.7 14.969,19.4 15.219,19.65 16.1,19.65 X1.3
N351754: U1.8 X1.1 | length 1.7
  Top Layer w0.127: U1.8 14.95,19.8 15.2,20.05 15.8,20.05 15.85,20.1 X1.1@15.85,20.15
N657194: LED100.2 R210.2 | length 3
  Top Layer w0.1: LED100.2 4.725,3.125 v1(4.725,1.975)
  Bottom Layer w0.1: v1(4.725,1.975) 4.825,1.975 4.9,2.05 R210.2
N657198: LED100.1 R211.2 | length 5.1
  Top Layer w0.1: LED100.1 4.025,1.925 v1(4.075,1.975)
  Signal Layer 3 w0.1: v1(4.075,1.975) 4.55,1.5 7.05,1.5 v1(6.95,1.6)
  Bottom Layer w0.1: v1(6.95,1.6) R211.2@7.6,1.6
N691250: C108.1 C109.1 L104.2 U1.27 | length 3.6
  Top Layer w0.2: U1.27 11.7,15.664 12.35,15.014 C109.1 C108.1 13.525,14.9 L104.2
N691286: C104.1 C105.1 L102.2 U1.25 | length 3.4
  Top Layer w0.2: L102.2 8.9,15 C104.1@8.95,14.95 ; C104.1 9.325,15.3 9.45,15.3 9.9,15.75 10.575,15.75 10.9,16.075 U1.25
N691370: C106.1 C107.1 L103.2 U1.26 | length 4.2
  Top Layer w0.2: L103.2@9.85,13.35 10.275,13.775 10.275,14.464 C106.1@10.711,14.9 ; 11.3,15.05 U1.26
  Top Layer w0.305: C106.1@10.75,15.05 11.3,15.05 11.55,15.05 C107.1
N692267: C110.1 C111.1 L105.1 U1.24 | length 2.6
  Top Layer w0.2: 9.4,17 U1.24
  Top Layer w0.305: L105.1 9.25,16.1 C111.1 ; C111.1@9.4,16.6 9.4,17 C110.1@9.4,17.375
N692925: C100.1 C101.1 L100.2 U1.10 | length 3.4
  Top Layer w0.203: U1.10 13.3,20.85 13.65,21.2 14.175,21.2 14.575,21.6 14.775,21.6 15.277,22.102 L100.2@15.752,22.102
N826284: C2.1 L1.2 L2.1 | length 1.2
  Top Layer w0.203: L1.2 C2.1 L2.1 L2.1@12.5,24.225
TP_TDI: P200.8 P200.16 R212.1 TPJ4.1 | length 24.8
  Signal Layer 3 w0.1: v1(6.8,29) 7.2,29.4 10.325,29.4 v1(10.725,29) 11.925,27.8 16.4,27.8 18.5,25.7 18.5,24 19,23.5 v1(19,20.5)
  Bottom Layer w0.1: P200.8 P200.8@6.745,31.045 ; v1(10.725,29) 11.225,29.5 11.5,29.5 11.825,29.825 P200.16 ; R212.1 v1@19.05,20.5 ; v1(19,20.5) 19,19.6 TPJ4.1
  Bottom Layer w0.2: P200.8 6.65,30.355 6.8,30.205 v1(6.8,29)
USB_VBUS: P200.35
USB_VREG: P200.36
VMCU: C203.1 C205.1 L100.1 L101.1 L102.1 L103.1 L104.1 L105.2 P300.1 R201.2 R202.2 R205.1 R208.1 TPJ11.1 | length 111.6
  Top Layer w0.3: v1(6.3,15.9) L105.2@7.95,15.9 ; L105.2@7.9,15.85 L105.2
  Top Layer w0.305: L103.1@9.95,12.325 v1(10.6,12.325) ; v1(13.95,12.775) L104.1
  Top Layer w0.4: v1(8.25,13.25) L102.1 ; v1(9.075,23.775) 9.075,23.4 L101.1@9.325,23.15
  Top Layer w0.5: L100.1@15.8,23.2 v1(16.25,23.2)
  Signal Layer 3 w0.1: v1(1.35,9.775) 1.2,9.925 1.2,18.866 1.2,19 3,20.8 v1(3,22.3) v1(3,24.8) ; v1(22.425,15.038) 23.2,14.262 23.2,9.6 24.25,8.55 25.75,8.55 ; v1(3,24.8) 3.075,24.8 3.025,24.85 3,24.825 v1(3,24.8)
  Signal Layer 3 w0.5: 11.45,20.925 13.525,20.925 15.8,23.2 v1(16.25,23.2)
  Signal Layer 3 w0.508: v1(5.25,10.025) 5.35,10.025 5.375,10.05 5.375,9.1 4.521,8.246 4.521,6.679 4.675,6.525 4.675,4.725 5.604,3.796 24.596,3.796 25.75,4.95 25.75,8.55 26.6,9.4 v1(26.6,13.7) ; v1@10.65,12.375 13.55,12.375 v1(13.95,12.775)
  Signal Layer 3 w0.6: v1(6.3,15.9) 7.1,15.9 ; v1(7,16.6) 7,16 7.1,15.9 ; 8.3,12.375 8.3,14.7 ; v1(9.075,23.775) 9.275,23.775 11.45,21.6 11.45,20.95 ; 11.45,20.925 10.3,19.775 10.3,16.7 8.3,14.7 ; 7.1,15.9 8.3,14.7
  Signal Layer 3 w1: 5.35,10.3 5.35,11.025 6.7,12.375 8.3,12.375 v1@10.625,12.375
  Bottom Layer w0.1: v1(1.35,9.775) v1@1.475,9.775 ; v1@1.5,9.8 v1@1.475,9.775 ; C203.1@2.65,9.225 2.4,9.475 1.65,9.475 1.475,9.65 v1@1.475,9.775 ; v1(3,22.3) 3.05,22.25 R205.1 ; v1(3,24.8) 3.975,24.8 R202.2 ; R208.1 v1(22.425,15.038) ; v1@26.45,13.85 v1(26.6,13.7)
  Bottom Layer w0.15: v1(9.075,23.775) 9.125,23.775 9.1,23.75 v1@9.088,23.737
  Bottom Layer w0.5: C203.1@2.9,9.075 R201.2 3.775,9.1 3.775,10.5 C205.1@3.8,10.525 ; C205.1@3.925,10.55 5.1,10.55 5.1,10.325 v1@5.25,10.175 ; v1(5.25,10.025) v1@5.25,10.175 ; v1(5.25,10.7) v1@5.25,10.175
  Bottom Layer w0.508: v1(26.6,13.7) 26.6,14.65 TPJ11.1@26.65,14.7
  Bottom Layer w0.6: v1(6.3,15.9) P300.1@7,15.9 ; P300.1@7,15.925 P300.1 ; P300.1@7,16 v1(7,16.6)
VMCU_IN: C201.1 P201.2 R201.1 | length 2.7
  Bottom Layer w0.4: P201.2@2.85,6.535 P201.2 2.935,8.115 2.925,8.125 3.75,8.125 R201.1
WSTK_F5: P200.18 R202.1 R203.2 R204.2 | length 17.1
  Signal Layer 3 w0.1: v1(4.9,24.775) 5.6,25.475 5.6,29.1 6.425,29.925 12.975,29.925 v1(13.8,29.1)
  Bottom Layer w0.1: R202.1 v1(4.9,24.775) ; P200.18@13.095,31.105 P200.18 13.095,29.805 v1(13.8,29.1)
WSTK_F14: P200.27 R208.2 R209.2 | length 16.5
  Signal Layer 3 w0.1: v1(20.4,26) 21.7,24.7 21.7,20.675 19.725,18.7 19.725,17.075 19.9,16.9 19.9,14.8 v1(20.5,14.2)
  Bottom Layer w0.1: P200.27 19.445,26.955 v1(20.4,26) ; v1(20.5,14.2) 21.391,14.2 21.491,14.3 21.508,14.283 R209.2
WSTK_F15: P200.28 P201.8 R216.2 | length 39.3
  Signal Layer 3 w0.1: v1(7.5,7.8) 8.425,6.875 13.575,6.875 v1(15.5,8.8) 16.75,8.8 18,10.05 18,12.9 18.5,13.4 18.5,18.925 20.2,20.625 20.2,23.9 19,25.1 19,28.4 18.7,28.7 18.7,29.166 18.934,29.4 19.8,29.4 v1(20.2,29)
  Bottom Layer w0.1: P201.8 6.745,7.045 v1(7.5,7.8) ; R216.2 15.5,9.8 v1(15.5,8.8) ; P200.28 19.445,29.755 v1(20.2,29)
WSTK_F16: P200.29 P201.4 R213.2 | length 49.7
  Signal Layer 3 w0.1: v1(9.325,10.6) 7.9,9.175 6.7,9.175 v1(5.325,7.8) 5.7,7.426 5.7,4.834 6.159,4.375 13.15,4.375 15.675,6.9 17.8,6.9 20.9,10 20.9,16.3 20.1,17.1 20.1,18.65 22.2,20.75 22.2,24.9 v1(21.2,25.9)
  Bottom Layer w0.1: v1(5.325,7.8) 4.925,7.8 P201.4@4.4,7.275 ; v1(9.325,10.6) 9.525,10.8 R213.2 R213.2@10.275,10.925 ; P200.29 20.715,26.885 21.2,26.4 v1(21.2,25.9) ; P201.4@4.4,7.275 4.205,7.08 P201.4 4.4,6.645 P201.4@4.4,7.275
WSTK_F21: P200.34
WSTK_P0: P201.3 R214.2 | length 11.5
  Signal Layer 3 w0.1: v1(5.3,5.025) 5.3,7.26 4.925,7.635 4.925,7.966 6.584,9.625 7.625,9.625 v1(8.525,10.525)
  Bottom Layer w0.1: P201.3 4.205,4.18 4.75,4.725 5,4.725 v1(5.3,5.025) ; v1(8.525,10.525) 8.525,10.225 8.85,9.9 R214.2 R214.2@9.33,10.07
WSTK_P2: P201.5 R217.2 | length 14.3
  Signal Layer 3 w0.1: v1(6.1,5) 6.5,4.6 6.911,4.6 7.2,4.889 7.2,5.3 8.375,6.475 13.675,6.475 15.05,7.85 15.325,7.85 v1(15.651,8.175)
  Bottom Layer w0.1: P201.5 5.475,3.775 5.788,4.088 5.788,4.688 v1(6.1,5) ; v1(15.651,8.175) 15.7,8.175 16.2,8.675 R217.2
WSTK_P12: P201.15 R215.2 | length 6
  Bottom Layer w0.1: R215.2 11.2,8.2 11.2,4.8 11.825,4.175 P201.15
WSTK_P13: P201.16 R218.2 | length 9
  Signal Layer 3 w0.1: v1(11.675,7.875) 11.675,7.925 11.7,7.95 11.75,7.9 12.05,8.2 13.817,8.2 16.282,10.665 16.887,10.665 v1(16.951,10.601)
  Bottom Layer w0.1: P201.16@11.7,6.4 v1@11.7,7.875 ; R218.2 16.45,10.65 17,10.65 v1(16.951,10.601)
WSTK_P15: P201.18
WSTK_P17: P201.20
WSTK_P19: P201.22
WSTK_P21: P201.24
WSTK_P23: P201.26
WSTK_P24: P201.27
WSTK_P26: P201.29
WSTK_P28: P201.31
WSTK_P29: P201.32
WSTK_P30: P201.33
WSTK_P32: P201.35
WSTK_P33: P201.36
WSTK_P34: P201.37
WSTK_P35: P201.38
WSTK_P37: P200.4 R205.2 R206.2 R207.1 | length 9.6
  Signal Layer 3 w0.1: v1(4.25,29) 4.4,28.85 4.4,22.45 v1(4.75,22.1)
  Bottom Layer w0.1: R206.2 v1(4.75,22.1) ; P200.4 4.25,30.405 v1@4.25,29.04
WSTK_P38: P200.5
WSTK_P39: P200.6
WSTK_P40: P200.7
WSTK_P43: P200.10
WSTK_P44: P200.11
WSTK_P45: P200.12
pads on no net: P200.M1 P200.M2 P201.40 P201.M1 P201.M2 TPJ9.1 TPJ18.1 TPJ19.1 TPJ20.1 U1.0@11.65,17.75 U1.0@11.65,19.05 U1.0@12.95,17.75 U1.0@12.95,19.05 U200.9

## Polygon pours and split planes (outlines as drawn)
GND on Signal Layer 2 "GND-L2" (solid, remove dead copper, pour order 34): 0,0 30,0 30,34.6 0,34.6
GND on Signal Layer 3 "GND-L2" (solid, remove dead copper, pour order 38): 0,0 30,0 30,34.6 0,34.6
GND on Bottom Layer "GND-L2" (solid, remove dead copper, pour order 40): 0,0 30,0 30,34.6 0,34.6
GND on Top Layer "GND-L2" (solid, remove dead copper, pour order 42): 0,0 30,0 30,34.6 0,34.6

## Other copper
Top Layer:
  pour cut-out: 15.025,20.775 15.263,21.013 16.063,21.013 16.6,21.55 17.075,21.55 17.475,21.15 17.475,18.137 15.025,18.137
  pour cut-out: 13,24.725 13,24.175 13.125,24.05 13.775,24.05 13.95,23.875 13.95,23.4 13.813,23.263 13.113,23.263 13,23.15 13,22.525 13.2,22.325 13.9,22.325 14.295,21.93 14.295,16.39 10.3,16.39 10.3,20.405 12,20.405 12,23.6 12,25.4 12.475,25.875 13.725,25.875 14,25.6 14,25.1 13.775,24.875 13.15,24.875
Signal Layer 2:
  pour cut-out: 18.277,30.375 18.277,32.075 16.173,32.075 16.173,31.806 14.877,31.806 14.877,30.637 16.172,30.637 16.172,30.376

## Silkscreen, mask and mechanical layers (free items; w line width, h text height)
Top Overlay:
  text "Wireless Gecko" at 0.85,41.4 h4.3
  text "2.4 GHz" at 1,39 h1.9
  text "20 dBm" at 1,37 h1.9
  text "EFR32xG21" at 0,8.228 h1.9
Bottom Overlay:
  lines w0.15: 1.5,38 1.5,37 2.5,37 ; 1.5,42 1.5,43 2.5,43 ; 19.5,37 20.5,37 20.5,38 ; 19.5,43 20.5,43 20.5,42
  lines w0.152: 2.6,21.125 2.6,20.825 2.9,20.825 ; 2.6,21.525 2.6,21.825 2.9,21.825 ; 2.6,23.675 2.6,23.375 2.9,23.375 ; 2.6,24.075 2.6,24.375 2.9,24.375 ; 3.2,21.825 3.5,21.825 3.5,22.125 ; 3.2,24.375 3.5,24.375 3.5,24.675 ; 3.5,22.425 3.5,22.725 3.8,22.725 ; 3.5,24.975 3.5,25.275 3.8,25.275 ; 3.55,20.925 3.55,20.825 3.8,20.825 ; 3.55,23.475 3.55,23.375 3.8,23.375 ; 4.2,20.825 4.45,20.825 4.45,20.925 ; 4.2,22.725 4.5,22.725 4.5,22.425 ; 4.2,23.375 4.45,23.375 4.45,23.475 ; 4.2,25.275 4.5,25.275 4.5,24.975 ; 4.5,22.125 4.5,21.825 4.8,21.825 ; 4.5,24.675 4.5,24.375 4.8,24.375 ; 5.1,20.825 5.4,20.825 5.4,21.125 ; 5.1,21.825 5.4,21.825 5.4,21.525 ; 5.1,23.375 5.4,23.375 5.4,23.675 ; 5.1,24.375 5.4,24.375 5.4,24.075 ; 21.05,13.25 21.05,12.95 21.35,12.95 ; 21.05,14.5 21.05,14.8 21.35,14.8 ; 21.7,12.95 22,12.95 22,13.25 ; 22,13.5 22,13.8 22.3,13.8 ; 22.6,13.8 22.925,13.8 22.925,14.1 ; 22.6,14.8 22.925,14.8 22.925,14.5
  text "BOARD INFO" at 20.55,43.35 h1.6
  text "PCB4180A Rev. A01" at 28.6,26 h1.52 r90
  text "ON" at 3.1,25.2 h1.2
  text "PD04" at 6.4,23.9 h1.2 r90
  text "OFF" at 2.3,23.45 h1.2
  text "VCOM / Enable" at 11.35,23.375 h1.6
  text "ON" at 3.075,22.2 h1.2
  text "OFF" at 2.3,20.95 h1.2
  text "Sensor / Enable" at 11.625,20.225 h1.6
  text "+" at 8.1,16.5 h1.52
  text "Disp Enable" at 25.114,15.294 h1.6
  text "ON" at 24.575,13.95 h1.2
  text "PD04" at 20.914,13.54 h1.2
  text "-" at 8.1,12.623 h1.52
  text "PC02" at 16.6,11.6 h1.6
  text "PC00" at 10.8,11.5 h1.6
  text "EXP16" at 14.6,10.6 h1.2
  text "EXP4" at 8.8,10.5 h1.2
  text "EXP8" at 14.6,9.6 h1.2
  text "EXP3" at 8.8,9.5 h1.2
  text "EXP5" at 14.6,8.7 h1.2
  text "EXP15" at 8.8,8.6 h1.2
Top Solder:
  the board outline again, w1
Bottom Solder:
  the board outline again, w1
BOARD OUTLINE 1:
  the board outline again, w0.1
Mechanical 11:
  the board outline again, w0.1
Mechanical 12:
  the board outline again, w0.1
EXT_SILKP 21:
  text "Blue Gecko" at 0.85,41.4 h4.3
  text "2.4 GHz" at 1,39 h1.9
  text "10 dBm" at 1,37 h1.9
  text "EFR32BG13" at 10.5,8.25 h1.9
EXT_SILKS 22:
  lines w0.152: 3.225,24.375 3.225,24.075 3.525,24.075 ; 3.225,24.725 3.225,25.025 3.525,25.025 ; 3.76,12.428 3.76,12.128 4.06,12.128 ; 3.76,13.678 3.76,13.978 4.06,13.978 ; 3.775,24.075 4.075,24.075 4.075,23.775 ; 4.075,23.475 4.075,23.15 4.375,23.15 ; 4.41,12.128 4.71,12.128 4.71,12.428 ; 4.71,12.678 4.71,12.978 5.01,12.978 ; 4.775,23.15 5.075,23.15 5.075,23.475 ; 4.775,25.025 5.075,25.025 5.075,24.725 ; 5.31,12.978 5.635,12.978 5.635,13.278 ; 5.31,13.978 5.635,13.978 5.635,13.678 ; 21.05,13.25 21.05,12.95 21.35,12.95 ; 21.05,14.5 21.05,14.8 21.35,14.8 ; 21.7,12.95 22,12.95 22,13.25 ; 22,13.5 22,13.8 22.3,13.8 ; 22.6,13.8 22.925,13.8 22.925,14.1 ; 22.6,14.8 22.925,14.8 22.925,14.5
  text "BOARD INFO" at 20.55,43.35 h1.6
  text "PCB4104A Rev A00" at 28.6,26 h1.52 r90
  text "Sensor Enable" at 10.102,25.651 h1.6
  text "ON" at 2.95,24.2 h1.2
  text "PD15" at 7.7,23.75 h1.2
  text "Disp Enable" at 25.114,15.294 h1.6
  text "PAVDD" at 6.733,14.636 h1.6
  text "ON" at 24.575,13.95 h1.2
  text "PD15" at 20.914,13.54 h1.2
  text "VDCDC" at 9.487,12.972 h1.2
  text "VMCU" at 3.658,12.596 h1.2
Mechanical 26:
  lines w0.2: -125.405,-47.962 -120.405,-47.962 ; -125.405,-0.962 -120.405,-0.962 ; -125.393,46.038 -120.405,46.038 ; -54.197,-94.993 -54.197,-89.993 ; -54.197,90.007 -54.197,95.007 ; 17.103,-94.993 17.103,-89.993 ; 17.103,90.007 17.103,95.007 ; 88.303,-94.993 88.303,-89.993 ; 88.303,90.007 88.303,95.007 ; 154.595,-47.962 159.595,-47.962 ; 154.595,-0.962 159.595,-0.962 ; 154.595,46.038 159.583,46.038 ; -125.393,-94.993 159.595,-94.993 159.595,94.999 -125.393,94.999 -125.393,-94.993 ; -120.405,-89.993 154.595,-89.993 154.595,90.007 -120.405,90.007 -120.405,-89.993
  text "1" at -92.505,91.578 h1.52
  text "2" at -20.197,91.578 h1.52
  text "3" at 52.403,91.578 h1.52
  text "4" at 123.203,91.578 h1.52
  text "D" at 156.593,72.438 h1.52
  text "D" at -123.518,71.233 h1.52
  text "C" at -123.518,23.738 h1.52
  text "C" at 156.466,23.738 h1.52
  text "B" at -123.518,-23.862 h1.52
  text "B" at 156.466,-23.862 h1.52
  text "A" at -123.518,-71.362 h1.52
  text "A" at 156.466,-71.362 h1.52
  text "1" at -91.285,-93.435 h1.52
  text "2" at -20.197,-93.435 h1.52
  text "3" at 52.103,-93.435 h1.52
  text "4" at 122.803,-93.435 h1.52
Mechanical 27:
  circle w0.152: c70.608,-68.539 r0.762
  circle w0.152: c70.608,-68.539 r1.778
  circle w0.254: c38.623,-82.995 r2.962
  lines w0.152: 59.609,-68.539 66.975,-68.539 ; 68.322,-68.539 72.894,-68.539 ; 60.371,-69.301 66.188,-70.317 66.213,-66.761 60.371,-67.777 60.371,-69.301
  lines w0.2: 34.575,-89.929 34.575,-63.069 74.589,-63.069 ; 34.575,-75.705 154.539,-75.705 ; 34.589,-72.069 74.589,-72.069 ; 54.869,-89.878 54.869,-75.781 ; 54.869,-72.022 54.869,-63.107 ; 134.589,-75.68 134.589,-72.069 ; 144.589,-72.069 144.589,-63.069 ; 154.589,-72.069 74.589,-72.069 ; 154.589,-63.069 74.589,-63.069 ; 74.589,-72.069 74.589,-63.069
  text "SIZE" at 36.589,-65.069 h1.52
  text "DOC NO" at 76.589,-65.069 h1.52
  text "REV" at 146.589,-65.069 h1.52
  text "PROJECTION" at 55.885,-65.418 h1.52
  text "'.Project_Revision'" at 146.309,-69.99 h2.54
  text "A4" at 39.239,-70.444 h2.54
  text "PCB4180" at 79.088,-70.444 h2.54
  text "REF" at 36.589,-74.069 h1.52
  text "SHEET" at 135.589,-74.069 h1.52
  text "1 of 2" at 145.43,-75.106 h1.52
  text "This drawing is confidential and is supplied on the express" at 55.352,-78.677 h1.52
  text "condition that it shall not be loaned, copied or disclosed to any" at 55.352,-81.217 h1.52
  text "other person or used for any purpose without the written consent of" at 55.352,-83.757 h1.52
  text "C" at 38.029,-84.011 h2.03
  text "2018" at 43.109,-84.163 h2.54
  text "SILICON LABS" at 55.784,-88.05 h2.54
Mechanical 28:
  lines w0.2: -125.404,-47.963 -120.404,-47.963 ; -125.404,-0.963 -120.404,-0.963 ; -125.392,46.037 -120.404,46.037 ; 154.596,-47.963 159.596,-47.963 ; 154.596,46.037 159.596,46.037
  lines w0.203: -120.429,-89.995 -120.429,90.005 ; -120.404,-89.995 154.596,-89.995 154.596,90.005 -120.404,90.005 ; -54.196,-94.995 -54.196,-89.995 ; -54.196,90.005 -54.196,95.005 ; 17.104,-94.995 17.104,-89.995 ; 17.104,90.005 17.104,95.005 ; 88.304,-94.995 88.304,-89.995 ; 88.304,90.005 88.304,95.005 ; -125.392,-94.995 159.596,-94.995 159.596,94.997 -125.392,94.997 -125.392,-94.995
  text "4" at -91.487,91.577 h1.52
  text "3" at -19.18,91.577 h1.52
  text "2" at 53.42,91.577 h1.52
  text "1" at 124.22,91.577 h1.52
  text "D" at 157.61,72.437 h1.52
  text "D" at -122.501,71.232 h1.52
  text "C" at -122.501,23.737 h1.52
  text "C" at 157.61,22.137 h1.52
  text "B" at -122.501,-23.863 h1.52
  text "B" at 157.61,-24.963 h1.52
  text "A" at 156.592,-71.287 h1.52
  text "A" at -122.501,-71.363 h1.52
  text "A" at 157.483,-71.363 h1.52
  text "4" at -90.268,-93.437 h1.52
  text "3" at -19.18,-93.437 h1.52
  text "2" at 52.967,-93.437 h1.52
  text "1" at 123.82,-93.437 h1.52
Mechanical 29:
  circle w0.152: c-36.251,-68.603 r0.762
  circle w0.152: c-36.251,-68.603 r1.778
  circle w0.254: c-4.266,-83.059 r2.962
  lines w0.152: -38.537,-68.603 -33.965,-68.603 ; -32.619,-68.603 -25.253,-68.603 ; -31.857,-66.825 -31.831,-70.381 -26.015,-69.365 -26.015,-67.841 -31.857,-66.825
  lines w0.2: -120.232,-72.134 -40.232,-72.134 ; -120.232,-63.134 -40.232,-63.134 ; -120.182,-75.769 -0.218,-75.769 ; -110.232,-72.134 -110.232,-63.134 ; -100.232,-75.744 -100.232,-72.134 ; -20.512,-89.943 -20.512,-75.846 ; -20.512,-72.086 -20.512,-63.171 ; -0.232,-72.134 -40.232,-72.134 ; -0.232,-63.134 -40.232,-63.134 ; -0.218,-89.993 -0.218,-63.069 ; -40.232,-72.134 -40.232,-63.134
  text "REV" at -112.232,-65.134 h1.52
  text "DOC NO" at -42.232,-65.134 h1.52
  text "SIZE" at -2.232,-65.134 h1.52
  text "PROJECTION" at -21.528,-65.482 h1.52
  text ".Project_Revision" at -111.952,-70.054 h2.54
  text "PCB4180" at -44.731,-70.508 h2.54
  text "A4" at -4.882,-70.508 h2.54
  text "SHEET" at -101.232,-74.134 h1.52
  text "REF" at -2.232,-74.134 h1.52
  text "2 of 2" at -110.92,-75.106 h1.52
  text "This drawing is confidential and is supplied on the express" at -20.995,-78.741 h1.52
  text "condition that it shall not be loaned, copied or disclosed to any" at -20.995,-81.281 h1.52
  text "other person or used for any purpose without the written consent of" at -20.995,-83.821 h1.52
  text "C" at -3.672,-84.075 h2.03
  text "2018" at -8.752,-84.228 h2.54
  text "SILICON LABS" at -21.427,-88.114 h2.54
Mechanical 30:
  lines w0.2: 34.575,-63.069 34.575,-42.23 154.575,-42.23 ; 34.575,-59.134 74.575,-59.134 ; 34.575,-55.134 74.575,-55.134 ; 34.575,-51.134 74.575,-51.134 ; 74.575,-55.135 154.575,-55.135 ; 74.575,-47.134 154.575,-47.134 ; 74.581,-63.069 74.581,-42.23 ; 74.581,-42.219 74.581,-32.025 154.625,-32.025
  text "BRD4180A: 2.4 GHz 20 dBm" at 75.65,-34.95 h1.8
  text "CUSTOMER" at 75.683,-44.146 h1.27
  text "PROJECT NO" at 36.059,-45.162 h1.52
  text "SILICON LABS" at 93.125,-46 h2.5
  text "DRAWING TITLE" at 75.912,-49.074 h1.52
  text "BRD4180" at 36,-50 h2.1
  text "DATE" at 36.059,-53.29 h1.52
  text "EFR32xG21 2.4 GHz 20 dBm Radio Board" at 75.825,-53.325 h1.8
  text "'.Print_Date'" at 54.347,-54.306 h1.52
  text "SHEET NAME" at 75.709,-57.227 h1.52
  text "DRAWN" at 36.059,-57.354 h1.52
  text "CHECK" at 36.059,-61.418 h1.52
